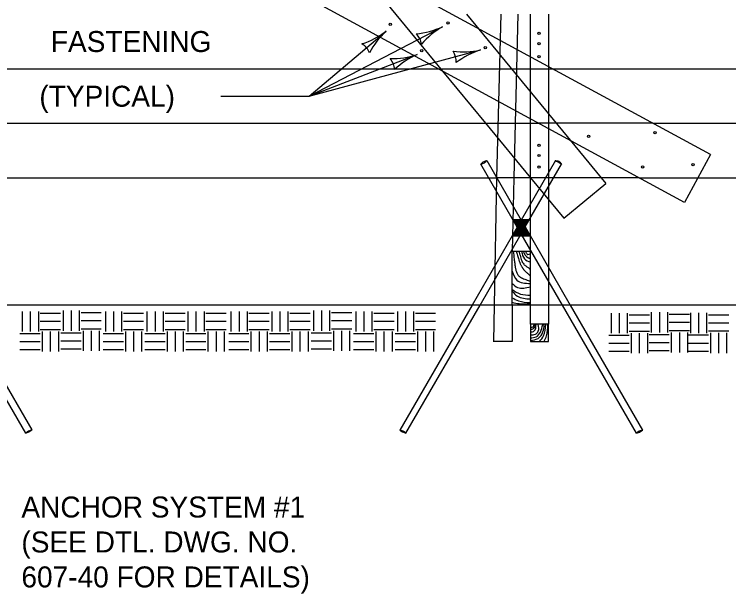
# Model space of a CAD drawing. Extents: x 49991 to 79985, y 47703 to 60542.
# Drawn here: x 50003.842 to 50005.885, y 49993.938 to 49995.596 of the extents above; entities that cross this region are included whole.
import ezdxf

# ---------------------------------------------------------------- set-up
doc = ezdxf.new("R2010")
doc.units = 0
for name, color, linetype in [('Level 1', 7, 'Continuous'), ('Level 2', 7, 'Continuous'), ('Level 3', 7, 'Continuous'), ('Level 4', 7, 'Continuous')]:
    doc.layers.add(name, color=color, linetype=linetype)

msp = doc.modelspace()

# ---------------------------------------------------------------- linework, layer by layer
at = {"layer": 'Level 1'}
for p, q in [((50005.833429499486, 49995.19463831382), (50001.4473, 49997.5783)), ((50005.7589714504, 49995.05761551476), (50001.372800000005, 49997.4412)), ((50001.079900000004, 49995.4403), (50005.05477163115, 49995.4403)), ((50005.066667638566, 49995.43383533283), (50005.189779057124, 49995.28430000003)), ((50005.38139220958, 49995.4403), (50006.0719, 49995.4403)), ((50001.079900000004, 49995.2843), (50005.34183623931, 49995.2843)), ((50005.668444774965, 49995.2843), (50006.0719, 49995.2843)), ((50005.83342949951, 49995.19463831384), (50005.7589714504, 49995.05761551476)), ((50005.2804, 49994.9876), (50005.176400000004, 49995.1678)), ((50005.1933, 49995.1776), (50005.2917, 49995.0072)), ((50005.39, 49995.177500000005), (50005.2917, 49995.0072)), ((50005.302907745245, 49994.987713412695), (50005.4069, 49995.1678)), ((50001.079900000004, 49995.128300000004), (50005.2215, 49995.128300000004)), ((50005.21513493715, 49994.7643), (50005.222200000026, 49995.128300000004)), ((50005.628900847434, 49995.128300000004), (50005.2215, 49995.128300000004)), ((50005.2709, 49995.128300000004), (50005.2656, 49994.9185)), ((50005.3179, 49994.7643), (50005.3179, 49995.128300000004)), ((50005.318279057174, 49995.128300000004), (50005.413368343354, 49995.012891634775)), ((50005.369900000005, 49995.128300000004), (50005.369900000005, 49994.7643)), ((50005.5206, 49995.128300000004), (50005.5339, 49995.112100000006)), ((50005.79738132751, 49995.128300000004), (50006.0719, 49995.128300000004)), ((50005.41336834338, 49995.012891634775), (50005.5339, 49995.112100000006)), ((50005.26793385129, 49995.0092), (50005.3153, 49995.0092)), ((50005.26943440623, 49995.0066), (50005.3138, 49995.0066)), ((50005.270934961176, 49995.004), (50005.312300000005, 49995.004)), ((50005.2804, 49994.9876), (50005.15142414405, 49994.7643)), ((50005.27243551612, 49995.0014), (50005.3108, 49995.0014)), ((50005.27393607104, 49994.9988), (50005.309309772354, 49994.9988)), ((50005.27543662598, 49994.9962), (50005.30780838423, 49994.9962)), ((50005.276937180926, 49994.9936), (50005.306306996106, 49994.9936)), ((50005.27785860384, 49994.9832), (50005.305514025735, 49994.9832)), ((50005.27843773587, 49994.991), (50005.304805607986, 49994.991)), ((50005.279360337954, 49994.9858), (50005.3040126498, 49994.9858)), ((50005.27993829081, 49994.9884), (50005.303304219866, 49994.9884)), ((50005.30290774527, 49994.987713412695), (50005.43191833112, 49994.7643)), ((50005.17392340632, 49994.7643), (50005.291600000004, 49994.9682)), ((50005.265844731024, 49994.962400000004), (50005.31752503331, 49994.962400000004)), ((50005.26734646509, 49994.965000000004), (50005.316023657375, 49994.965000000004)), ((50005.2688481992, 49994.9676), (50005.31452228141, 49994.9676)), ((50005.27034993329, 49994.9702), (50005.31302090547, 49994.9702)), ((50005.27185166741, 49994.9728), (50005.31151952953, 49994.9728)), ((50005.27335340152, 49994.9754), (50005.3100181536, 49994.9754)), ((50005.274855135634, 49994.978), (50005.30851677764, 49994.978)), ((50005.27635686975, 49994.9806), (50005.3070154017, 49994.9806)), ((50005.409318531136, 49994.7643), (50005.291600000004, 49994.9682)), ((50005.2656, 49994.9185), (50005.3179, 49994.9185)), ((50005.2656, 49994.7643), (50005.2656, 49994.9185)), ((50005.3179, 49994.7643), (50005.3179, 49994.842300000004)), ((50007.8111, 49994.7643), (50000.0394, 49994.7643)), ((50003.8645, 49994.7463), (50003.8645, 49994.6884)), ((50003.8876, 49994.7463), (50003.8876, 49994.6884)), ((50003.910800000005, 49994.7463), (50003.910800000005, 49994.6884)), ((50003.9161, 49994.740900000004), (50003.973900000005, 49994.740900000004)), ((50003.981400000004, 49994.748400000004), (50003.981400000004, 49994.690500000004)), ((50004.0045, 49994.748400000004), (50004.0045, 49994.690500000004)), ((50004.027700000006, 49994.748400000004), (50004.027700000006, 49994.690500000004)), ((50004.033, 49994.743), (50004.090800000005, 49994.743)), ((50004.1025, 49994.7463), (50004.1025, 49994.6884)), ((50004.1256, 49994.7463), (50004.1256, 49994.6884)), ((50004.148700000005, 49994.7463), (50004.148700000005, 49994.6884)), ((50004.1541, 49994.740900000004), (50004.2119, 49994.740900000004)), ((50004.2215, 49994.7463), (50004.2215, 49994.6884)), ((50004.244600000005, 49994.7463), (50004.244600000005, 49994.6884)), ((50004.267700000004, 49994.7463), (50004.267700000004, 49994.6884)), ((50004.273100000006, 49994.740900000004), (50004.3309, 49994.740900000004)), ((50004.3384, 49994.7463), (50004.3384, 49994.6884)), ((50004.3615, 49994.7463), (50004.3615, 49994.6884)), ((50004.384600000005, 49994.7463), (50004.384600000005, 49994.6884)), ((50004.39, 49994.740900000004), (50004.4478, 49994.740900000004)), ((50004.461500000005, 49994.7463), (50004.461500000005, 49994.6884)), ((50004.4847, 49994.7463), (50004.4847, 49994.6884)), ((50004.5078, 49994.7463), (50004.5078, 49994.6884)), ((50004.5132, 49994.740900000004), (50004.571, 49994.740900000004)), ((50004.578400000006, 49994.7463), (50004.578400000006, 49994.6884)), ((50004.6016, 49994.7463), (50004.6016, 49994.6884)), ((50004.6247, 49994.7463), (50004.6247, 49994.6884)), ((50004.6301, 49994.740900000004), (50004.687900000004, 49994.740900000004)), ((50004.697400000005, 49994.748400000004), (50004.697400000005, 49994.690500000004)), ((50004.7206, 49994.748400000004), (50004.7206, 49994.690500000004)), ((50004.7437, 49994.748400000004), (50004.7437, 49994.690500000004)), ((50004.7491, 49994.743), (50004.8069, 49994.743)), ((50004.8185, 49994.7463), (50004.8185, 49994.6884)), ((50004.8416, 49994.7463), (50004.8416, 49994.6884)), ((50004.8648, 49994.7463), (50004.8648, 49994.6884)), ((50004.8701, 49994.740900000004), (50004.928, 49994.740900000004)), ((50004.9375, 49994.7463), (50004.9375, 49994.6884)), ((50004.960600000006, 49994.7463), (50004.960600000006, 49994.6884)), ((50004.9838, 49994.7463), (50004.9838, 49994.6884)), ((50004.9891, 49994.740900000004), (50005.0469, 49994.740900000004)), ((50005.548800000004, 49994.741500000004), (50005.548800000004, 49994.683600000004)), ((50005.5719, 49994.741500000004), (50005.5719, 49994.683600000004)), ((50005.595, 49994.741500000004), (50005.595, 49994.683600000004)), ((50005.6636, 49994.743500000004), (50005.6636, 49994.6857)), ((50005.686700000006, 49994.743500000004), (50005.686700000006, 49994.6857)), ((50005.7099, 49994.743500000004), (50005.7099, 49994.6857)), ((50005.715200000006, 49994.7382), (50005.773, 49994.7382)), ((50005.7756, 49994.7419), (50005.7756, 49994.684100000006)), ((50005.7987, 49994.7419), (50005.7987, 49994.684100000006)), ((50005.821800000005, 49994.7419), (50005.821800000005, 49994.684100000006)), ((50003.9161, 49994.717800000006), (50003.973900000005, 49994.717800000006)), ((50004.033, 49994.719900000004), (50004.090800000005, 49994.719900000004)), ((50004.1541, 49994.717800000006), (50004.2119, 49994.717800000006)), ((50004.273100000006, 49994.717800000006), (50004.3309, 49994.717800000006)), ((50004.39, 49994.717800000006), (50004.4478, 49994.717800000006)), ((50004.5132, 49994.717800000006), (50004.571, 49994.717800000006)), ((50004.6301, 49994.717800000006), (50004.687900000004, 49994.717800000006)), ((50004.7491, 49994.719900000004), (50004.8069, 49994.719900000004)), ((50004.8701, 49994.717800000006), (50004.928, 49994.717800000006)), ((50004.9891, 49994.717800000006), (50005.0469, 49994.717800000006)), ((50005.6004, 49994.7361), (50005.658200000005, 49994.7361)), ((50005.8272, 49994.736600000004), (50005.885, 49994.736600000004)), ((50004.033, 49994.6967), (50004.090800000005, 49994.6967)), ((50004.7491, 49994.6967), (50004.8069, 49994.6967)), ((50005.6004, 49994.713), (50005.658200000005, 49994.713)), ((50005.715200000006, 49994.715000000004), (50005.773, 49994.715000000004)), ((50005.8272, 49994.7134), (50005.885, 49994.7134)), ((50003.8583, 49994.6831), (50003.9161, 49994.6831)), ((50003.9161, 49994.6946), (50003.973900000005, 49994.6946)), ((50003.9219, 49994.6889), (50003.9219, 49994.631)), ((50003.945, 49994.6889), (50003.945, 49994.631)), ((50003.968100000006, 49994.6889), (50003.968100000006, 49994.631)), ((50003.9752, 49994.6851), (50004.033, 49994.6851)), ((50004.0388, 49994.6909), (50004.0388, 49994.6331)), ((50004.0619, 49994.6909), (50004.0619, 49994.6331)), ((50004.085, 49994.6909), (50004.085, 49994.6331)), ((50004.096300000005, 49994.6831), (50004.1541, 49994.6831)), ((50004.1541, 49994.6946), (50004.2119, 49994.6946)), ((50004.159900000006, 49994.6889), (50004.159900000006, 49994.631)), ((50004.183000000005, 49994.6889), (50004.183000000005, 49994.631)), ((50004.2061, 49994.6889), (50004.2061, 49994.631)), ((50004.2153, 49994.6831), (50004.273100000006, 49994.6831)), ((50004.273100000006, 49994.6946), (50004.3309, 49994.6946)), ((50004.278900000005, 49994.6889), (50004.278900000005, 49994.631)), ((50004.302, 49994.6889), (50004.302, 49994.631)), ((50004.3251, 49994.6889), (50004.3251, 49994.631)), ((50004.332200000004, 49994.6831), (50004.39, 49994.6831)), ((50004.39, 49994.6946), (50004.4478, 49994.6946)), ((50004.395800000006, 49994.6889), (50004.395800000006, 49994.631)), ((50004.418900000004, 49994.6889), (50004.418900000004, 49994.631)), ((50004.442, 49994.6889), (50004.442, 49994.631)), ((50004.4553, 49994.6831), (50004.5132, 49994.6831)), ((50004.5132, 49994.6946), (50004.571, 49994.6946)), ((50004.5189, 49994.6889), (50004.5189, 49994.631)), ((50004.542100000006, 49994.6889), (50004.542100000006, 49994.631)), ((50004.565200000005, 49994.6889), (50004.565200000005, 49994.631)), ((50004.5722, 49994.6831), (50004.6301, 49994.6831)), ((50004.6301, 49994.6946), (50004.687900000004, 49994.6946)), ((50004.635800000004, 49994.6889), (50004.635800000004, 49994.631)), ((50004.659, 49994.6889), (50004.659, 49994.631)), ((50004.682100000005, 49994.6889), (50004.682100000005, 49994.631)), ((50004.6912, 49994.6851), (50004.7491, 49994.6851)), ((50004.7548, 49994.6909), (50004.7548, 49994.6331)), ((50004.778000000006, 49994.6909), (50004.778000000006, 49994.6331)), ((50004.801100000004, 49994.6909), (50004.801100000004, 49994.6331)), ((50004.812300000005, 49994.6831), (50004.8701, 49994.6831)), ((50004.8701, 49994.6946), (50004.928, 49994.6946)), ((50004.8759, 49994.6889), (50004.8759, 49994.631)), ((50004.899000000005, 49994.6889), (50004.899000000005, 49994.631)), ((50004.9222, 49994.6889), (50004.9222, 49994.631)), ((50004.931300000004, 49994.6831), (50004.9891, 49994.6831)), ((50004.9891, 49994.6946), (50005.0469, 49994.6946)), ((50004.994900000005, 49994.6889), (50004.994900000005, 49994.631)), ((50005.018000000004, 49994.6889), (50005.018000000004, 49994.631)), ((50005.0411, 49994.6889), (50005.0411, 49994.631)), ((50005.5426, 49994.6782), (50005.6004, 49994.6782)), ((50005.6004, 49994.6898), (50005.658200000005, 49994.6898)), ((50005.6062, 49994.684), (50005.6062, 49994.6262)), ((50005.6293, 49994.684), (50005.6293, 49994.6262)), ((50005.6524, 49994.684), (50005.6524, 49994.6262)), ((50005.657400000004, 49994.6803), (50005.715200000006, 49994.6803)), ((50005.715200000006, 49994.691900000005), (50005.773, 49994.691900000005)), ((50005.721000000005, 49994.6861), (50005.721000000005, 49994.628300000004)), ((50005.7441, 49994.6861), (50005.7441, 49994.628300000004)), ((50005.7672, 49994.6861), (50005.7672, 49994.628300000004)), ((50005.7693, 49994.678700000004), (50005.8272, 49994.678700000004)), ((50005.8272, 49994.6903), (50005.885, 49994.6903)), ((50005.8329, 49994.6845), (50005.8329, 49994.6267)), ((50005.856100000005, 49994.6845), (50005.856100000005, 49994.6267)), ((50005.8792, 49994.6845), (50005.8792, 49994.6267)), ((50003.8583, 49994.66), (50003.9161, 49994.66)), ((50003.9752, 49994.662000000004), (50004.033, 49994.662000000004)), ((50004.096300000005, 49994.66), (50004.1541, 49994.66)), ((50004.2153, 49994.66), (50004.273100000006, 49994.66)), ((50004.332200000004, 49994.66), (50004.39, 49994.66)), ((50004.4553, 49994.66), (50004.5132, 49994.66)), ((50004.5722, 49994.66), (50004.6301, 49994.66)), ((50004.6912, 49994.662000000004), (50004.7491, 49994.662000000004)), ((50004.812300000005, 49994.66), (50004.8701, 49994.66)), ((50004.931300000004, 49994.66), (50004.9891, 49994.66)), ((50005.5426, 49994.6551), (50005.6004, 49994.6551)), ((50005.657400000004, 49994.6572), (50005.715200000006, 49994.6572)), ((50005.7693, 49994.655600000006), (50005.8272, 49994.655600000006)), ((50003.8583, 49994.6368), (50003.9161, 49994.6368)), ((50003.9752, 49994.638900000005), (50004.033, 49994.638900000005)), ((50004.096300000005, 49994.6368), (50004.1541, 49994.6368)), ((50004.2153, 49994.6368), (50004.273100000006, 49994.6368)), ((50004.332200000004, 49994.6368), (50004.39, 49994.6368)), ((50004.4553, 49994.6368), (50004.5132, 49994.6368)), ((50004.5722, 49994.6368), (50004.6301, 49994.6368)), ((50004.6912, 49994.638900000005), (50004.7491, 49994.638900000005)), ((50004.812300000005, 49994.6368), (50004.8701, 49994.6368)), ((50004.931300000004, 49994.6368), (50004.9891, 49994.6368)), ((50005.5426, 49994.632000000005), (50005.6004, 49994.632000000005)), ((50005.657400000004, 49994.6341), (50005.715200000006, 49994.6341)), ((50005.7693, 49994.6325), (50005.8272, 49994.6325))]:
    msp.add_line(p, q, dxfattribs=at)
for centre in [(50005.08234799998, 49995.57153599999), (50004.91732599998, 49995.567376), (50005.34260799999, 49995.541558), (50005.34260799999, 49995.51243799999), (50005.007156, 49995.49246999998), (50005.18886999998, 49995.50078999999), (50005.34260799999, 49995.47502399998), (50005.48443799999, 49995.246900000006), (50005.67452399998, 49995.257326), (50005.34260799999, 49995.22134199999), (50005.34260799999, 49995.19222199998), (50005.78312599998, 49995.165754), (50005.34260799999, 49995.15894199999), (50005.639008, 49995.15951399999)]:
    msp.add_circle(centre, 0.0032708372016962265, dxfattribs=at)
for points in [[(50005.176400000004, 49995.1678), (50005.1866, 49995.171500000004), (50005.1933, 49995.1776)], [(50005.176400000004, 49995.1678), (50005.185900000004, 49995.1754), (50005.1933, 49995.1776)], [(50005.39, 49995.177500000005), (50005.401600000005, 49995.1743), (50005.4069, 49995.1678)], [(50005.39, 49995.177500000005), (50005.3985, 49995.172900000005), (50005.4069, 49995.1678)], [(50005.268639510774, 49994.918499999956), (50005.27162091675, 49994.895451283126), (50005.273101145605, 49994.88392512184), (50005.274600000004, 49994.8724), (50005.27492919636, 49994.87020546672), (50005.275349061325, 49994.8679668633), (50005.27647117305, 49994.863430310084), (50005.27991755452, 49994.85462986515), (50005.285105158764, 49994.84716448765), (50005.28840379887, 49994.84429676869), (50005.29023840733, 49994.84314290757), (50005.2922, 49994.8422), (50005.30504321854, 49994.83702027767), (50005.31789999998, 49994.831916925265)], [(50005.276814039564, 49994.918499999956), (50005.27894592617, 49994.912492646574), (50005.280914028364, 49994.906380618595), (50005.2847600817, 49994.89409894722), (50005.28576081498, 49994.89108244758), (50005.28683168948, 49994.88809058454), (50005.287965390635, 49994.88512011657), (50005.28915460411, 49994.88216780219), (50005.29041869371, 49994.8793009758), (50005.29180829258, 49994.8764939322), (50005.293293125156, 49994.87375796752), (50005.29408052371, 49994.872418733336), (50005.29448615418, 49994.87175674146), (50005.29469203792, 49994.8714277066), (50005.29479575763, 49994.87126368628), (50005.2949, 49994.871100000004), (50005.297300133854, 49994.86770976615), (50005.29861106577, 49994.866094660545), (50005.299987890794, 49994.86453098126), (50005.30291851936, 49994.86146480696), (50005.30597812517, 49994.85853865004), (50005.312329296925, 49994.85277699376), (50005.31547104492, 49994.84987453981), (50005.317900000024, 49994.84750989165)], [(50005.285079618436, 49994.918499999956), (50005.286212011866, 49994.91456434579), (50005.28725232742, 49994.91060574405), (50005.28929525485, 49994.90267882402), (50005.29168545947, 49994.89483749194), (50005.29315987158, 49994.8909858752), (50005.293992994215, 49994.88908379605), (50005.29443679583, 49994.88813949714), (50005.29466591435, 49994.8876691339), (50005.29478232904, 49994.8874344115), (50005.294841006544, 49994.88731716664), (50005.2949, 49994.887200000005), (50005.29927210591, 49994.88112774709), (50005.30494513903, 49994.87618271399), (50005.31114560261, 49994.8716963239), (50005.31420190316, 49994.869416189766), (50005.3171, 49994.867000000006)], [(50005.2928, 49994.9181), (50005.3009, 49994.8966), (50005.317800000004, 49994.887200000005)], [(50005.29677997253, 49994.91850000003), (50005.297452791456, 49994.91738865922), (50005.29809933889, 49994.9162594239), (50005.299342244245, 49994.9139667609), (50005.301827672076, 49994.90938110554), (50005.30469425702, 49994.905054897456), (50005.30641360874, 49994.90308654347), (50005.307369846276, 49994.90216810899), (50005.30787523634, 49994.90172745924), (50005.30813514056, 49994.90151204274), (50005.30826694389, 49994.9014055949), (50005.30833331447, 49994.90135269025), (50005.3084, 49994.901300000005), (50005.31043121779, 49994.90009301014), (50005.31262389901, 49994.899314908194), (50005.314879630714, 49994.89870435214), (50005.316000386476, 49994.89838023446), (50005.3171, 49994.898)], [(50005.303245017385, 49994.918499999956), (50005.3037050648, 49994.91785301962), (50005.3041427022, 49994.917141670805), (50005.30497277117, 49994.91558998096), (50005.306606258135, 49994.912419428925), (50005.308497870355, 49994.91001416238), (50005.309650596, 49994.90941907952), (50005.31029796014, 49994.90932952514), (50005.3106418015, 49994.90934375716), (50005.311, 49994.909400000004), (50005.3171, 49994.9107)], [(50005.265900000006, 49994.861000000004), (50005.2793, 49994.8354), (50005.317800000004, 49994.826100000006)], [(50005.265900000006, 49994.826100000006), (50005.2814, 49994.814600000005), (50005.3179, 49994.81666483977)], [(50005.2652, 49994.8093), (50005.290100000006, 49994.7958), (50005.317800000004, 49994.7925)], [(50005.265900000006, 49994.8039), (50005.2807, 49994.789800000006), (50005.3176, 49994.78188717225)], [(50005.265900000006, 49994.7851), (50005.284100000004, 49994.7764), (50005.317600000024, 49994.77113792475)], [(50005.265900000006, 49994.772300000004), (50005.286100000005, 49994.7683), (50005.3171, 49994.7683)]]:
    msp.add_spline(points, degree=3, dxfattribs=at)
at = {"layer": 'Level 3'}
for p, q in [((50004.6852, 49995.3618), (50005.066600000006, 49995.5608)), ((50004.6852, 49995.3618), (50004.9051, 49995.5481)), ((50004.6852, 49995.3618), (50005.175, 49995.4941)), ((50004.6852, 49995.3618), (50004.994300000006, 49995.481400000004)), ((50004.432630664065, 49995.3618), (50004.6852, 49995.3618))]:
    msp.add_line(p, q, dxfattribs=at)
for centre, radius, start, end in [((50004.97196315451, 49995.761974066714), 0.2223221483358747, 275.00985000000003, 295.1933583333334), ((50005.18443778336, 49995.3597988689), 0.23299613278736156, 120.38115, 139.631), ((50004.768497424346, 49995.7235048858), 0.2223221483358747, 287.72739166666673, 307.9109000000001), ((50005.06429625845, 49995.37797137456), 0.23299613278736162, 133.0986916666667, 152.3485416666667), ((50004.952927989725, 49995.501490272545), 0.054774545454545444, 9.692658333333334, 45.41501944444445), ((50004.807273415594, 49995.46522099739), 0.054774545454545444, 22.4102, 58.132561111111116), ((50005.12591521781, 49995.710935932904), 0.22232214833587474, 262.571475, 282.75498333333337), ((50005.24677840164, 49995.27243570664), 0.23299613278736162, 107.94277500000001, 127.192625), ((50004.92268090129, 49995.69187052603), 0.2223221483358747, 268.60895, 288.79245833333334), ((50005.08899468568, 49995.26851478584), 0.23299613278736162, 113.98025000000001, 133.23010000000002), ((50005.05122138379, 49995.46066612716), 0.054774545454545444, 357.2542833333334, 32.9766444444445), ((50004.87472448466, 49995.435132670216), 0.054774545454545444, 3.2917583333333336, 39.01411944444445)]:
    msp.add_arc(centre, radius, start, end, dxfattribs=at)
at = {"layer": 'Level 4'}
for p, q in [((50004.67580451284, 49995.9083), (50005.066667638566, 49995.43383533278)), ((50005.1351, 49995.596300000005), (50005.5206, 49995.128300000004)), ((50005.222200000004, 49995.128300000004), (50005.2339, 49995.596300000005)), ((50005.2823, 49995.596299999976), (50005.2709, 49995.128300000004)), ((50005.3179, 49995.128300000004), (50005.3179, 49995.596299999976)), ((50005.369900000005, 49995.596299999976), (50005.369900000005, 49995.128300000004)), ((50005.05477163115, 49995.4403), (50005.38139220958, 49995.4403)), ((50005.189779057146, 49995.2843), (50005.318279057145, 49995.128300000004)), ((50005.668444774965, 49995.2843), (50005.34183623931, 49995.2843)), ((50005.628900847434, 49995.128300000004), (50005.79738132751, 49995.128300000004)), ((50003.874800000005, 49994.397600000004), (50003.66306483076, 49994.764300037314)), ((50003.685665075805, 49994.764300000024), (50003.8919, 49994.407)), ((50005.15142378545, 49994.7643), (50004.9449, 49994.4066)), ((50004.962100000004, 49994.3974), (50005.17392373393, 49994.7643)), ((50005.21309971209, 49994.6603), (50005.21513493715, 49994.7643)), ((50005.2656, 49994.7643), (50005.2656, 49994.6603)), ((50005.3179, 49994.709200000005), (50005.3179, 49994.7643)), ((50005.369900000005, 49994.7643), (50005.369900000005, 49994.709200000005)), ((50005.62103610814, 49994.39733626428), (50005.409318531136, 49994.7643)), ((50005.43191840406, 49994.7643), (50005.6384, 49994.4067)), ((50005.265900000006, 49994.6603), (50005.211500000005, 49994.6603))]:
    msp.add_line(p, q, dxfattribs=at)
msp.add_lwpolyline([(50005.3179, 49994.6603), (50005.369900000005, 49994.6603), (50005.369900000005, 49994.709200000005), (50005.3179, 49994.709200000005)], close=True, dxfattribs=at)
for points in [[(50003.874800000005, 49994.397600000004), (50003.883700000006, 49994.4012), (50003.8919, 49994.407)], [(50003.89189999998, 49994.407), (50003.8824, 49994.4035), (50003.87480000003, 49994.397600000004)], [(50004.9449, 49994.4066), (50004.95234654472, 49994.401494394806), (50004.962100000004, 49994.39739999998)], [(50005.63839999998, 49994.4067), (50005.6289, 49994.4032), (50005.62101896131, 49994.39736598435)], [(50005.62103610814, 49994.39733626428), (50005.6302, 49994.4009), (50005.6384, 49994.4067)]]:
    msp.add_lwpolyline(points, dxfattribs=at)
for points in [[(50005.3176, 49994.6707), (50005.3344, 49994.6734), (50005.3533, 49994.708300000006)], [(50005.3182, 49994.7002), (50005.327000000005, 49994.7036), (50005.328400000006, 49994.708300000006)], [(50005.3182, 49994.6949), (50005.327000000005, 49994.6969), (50005.3324, 49994.708300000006)], [(50005.3182, 49994.6868), (50005.329000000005, 49994.690200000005), (50005.3344, 49994.708300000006)], [(50005.3182, 49994.6794), (50005.3324, 49994.6808), (50005.340500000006, 49994.6895), (50005.340500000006, 49994.708300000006)], [(50005.3182, 49994.6633), (50005.3398, 49994.6687), (50005.354, 49994.6875), (50005.3573, 49994.7076)], [(50005.3452, 49994.6606), (50005.3553, 49994.676), (50005.362100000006, 49994.708300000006)], [(50005.3573, 49994.6606), (50005.3641, 49994.676), (50005.3681, 49994.709)], [(50004.9449, 49994.4066), (50004.9551, 49994.4034), (50004.962100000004, 49994.3974)]]:
    msp.add_spline(points, degree=3, dxfattribs=at)

# ---------------------------------------------------------------- texts
at = {"layer": 'Level 2'}
for s, p in [('FASTENING', (50003.9466, 49995.488300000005)), ('(TYPICAL)', (50003.913700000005, 49995.3318)), ('ANCHOR SYSTEM #1', (50003.862400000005, 49994.1564)), ('(SEE DTL. DWG. NO.', (50003.862400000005, 49994.0564)), ('607-40 FOR DETAILS)', (50003.862400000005, 49993.9564))]:
    msp.add_text(s, height=0.060000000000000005, dxfattribs=at).set_placement(p)

doc.saveas('drawing.dxf')
